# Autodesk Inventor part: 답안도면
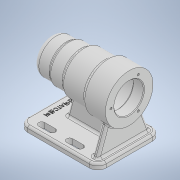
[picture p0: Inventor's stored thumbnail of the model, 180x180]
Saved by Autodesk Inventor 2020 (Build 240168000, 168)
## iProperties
Created: 2021-10
Part Number: 답안도면
Material: 일반
Document SubType Name: Modeling
Designer: user
Density: 1 g/cm^3
Appearance: 기본값
Author: user
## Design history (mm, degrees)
sketch "스케치1"
  geometry: L1 (0, 0)-(0, 34); L2 (0, 34)-(-32, 34); L3 (-32, 34)-(-32, 30); L4 (-32, 30)-(-66, 30); L5 (-66, 30)-(-66, 27); L6 (-66, 27)-(-88, 27); L7 (-88, 27)-(-88, 25); L8 (-88, 25)-(-112, 25); L9 (-112, 25)-(-112, 0); L10 (-112, 0)-(0, 0)
  constraints: 20 end point, 9 perpendicular, 1 vertical
  dimensions: "d0" = 24 distance of L7.end L8.end; "d1" = 46 distance between parallel lines of L5 L9; "d2" = 80 distance between parallel lines of L3 L9; "d3" = 112 distance between parallel lines of L1 L9; "d4" = 50 diameter of L8 L10; "d5" = 54 diameter of L6 L10; "d6" = 60 diameter of L4 L10; "d7" = 68 diameter of L2 L10
revolve "회전1" sketch "스케치1" stored, may be unused: angle "d8" = 90 deg
sketch "스케치2"
  geometry: C1 r 21 at (0, 0); 1 further point
  constraints: 1 centre point, 1 coincident
  dimensions: "d9" = 42 diameter of C1
extrude "돌출1" cut sketch "스케치2" distance "d10" = 15; taper "d11" = 0 deg
sketch "스케치3"
  geometry: C1 r 24 at (0, 0); 1 further point
  constraints: 1 centre point, 1 coincident
  dimensions: "d12" = 48 diameter of C1
extrude "돌출2" cut sketch "스케치3" distance "d13" = 54; taper "d14" = 0 deg
sketch "스케치4"
  geometry: C1 r 21 at (0, 0); 1 further point
  constraints: 1 centre point, 1 coincident
  dimensions: "d15" = 42 diameter of C1
extrude "돌출3" cut sketch "스케치4" distance "d16" = 12; taper "d17" = 0 deg
sketch "스케치5"
  geometry: C1 r 24 at (0, 0) reference; C2 r 17.5 at (0, 0); 1 further point
  constraints: 1 centre point, 1 coincident
  dimensions: "d18" = 35 diameter of C2
extrude "돌출4" cut sketch "스케치5" distance "d19" = 18; taper "d20" = 0 deg
sketch "스케치6"
  geometry: C1 r 16 at (0, 0); 1 further point
  constraints: 1 centre point, 1 coincident
  dimensions: "d21" = 32 diameter of C1
extrude "돌출5" cut sketch "스케치6" distance "d22" = 4; taper "d23" = 0 deg
sketch "스케치7"
  geometry: C1 r 21 at (0, 0) reference; C2 r 10.5 at (0, 0); 1 further point
  constraints: 1 centre point, 1 coincident
  dimensions: "d24" = 21 diameter of C2
extrude "돌출6" cut sketch "스케치7" distance "d25" = 3; taper "d26" = 0 deg
node "작업 평면1"
sketch "스케치10"
  geometry: L1 (112, 45)-(0, 45); L2 (0, 45)-(0, -45); L3 (0, -45)-(112, -45); L4 (112, -45)-(112, 45); L5 (112, 45)-(0, -45); L6 (0, 45)-(112, -45); L7 (112, 25)-(112, -25) reference; 3 further points
  constraints: 12 end point, 3 midpoint, 2 parallel, 1 horizontal, 1 horizontal alignment, 1 perpendicular, 1 point on line
  dimensions: "d28" = 112 distance of L3.end L2.end; "d29" = 90 distance of L2.end L1.end
extrude "돌출7" join sketch "스케치10" distance "d30" = 8; taper "d31" = 0 deg
sketch "스케치11"
  geometry: L1 (-85, -4)-(-8, -4); L2 (-8, -4)-(-8, 4); L3 (-8, 4)-(-85, 4); L4 (-85, 4)-(-85, -4); L5 (-85, -4)-(-8, 4); L6 (-8, -4)-(-85, 4); L7 (-112, -45)-(0, -45) reference; L8 (0, -45)-(0, 45) reference; 4 further points
  constraints: 12 end point, 4 midpoint, 2 parallel, 1 horizontal, 1 horizontal alignment, 1 perpendicular
  dimensions: "d34" = 8 distance between parallel lines of L8 L2; "d35" = 8 distance of L3.end L1.start; "d36" = 77 distance of L2.end L3.end
extrude "돌출8" join sketch "스케치11" stored distance "d37" = 8; taper "d38" = 0 deg
sketch "스케치12"
  geometry: L1 (-41, -8)-(-41, 0) reference; L2 (-41, 0)-(0, 0) reference; L3 (0, 0)-(0, 28.236) reference; L4 (8, 28.236)-(8, 0) reference; L5 (8, 0)-(49, 0) reference; L6 (49, 0)-(49, -8) reference; L7 (49, -8)-(-41, -8) reference; L8 (0, 0)-(8, 0) reference; L9 (-19.409, 37.342)-(-33, 0); L10 (49, 0)-(-41, 0) reference; C1 r 21 at (4, 62) reference; A1 r 34 centre (4, 62) between (8, 28.236) and (0, 28.236) reference; A2 r 34 centre (4, 62) between (0, 28.236) and (8, 28.236) reference; 2 further points
  constraints: 2 end point, 1 point on circle, 1 point on line
  dimensions: "d39" = 8 distance from line of L1 L9.end; "d40" = 110 deg angle of L2 L9
extrude "돌출9" join sketch "스케치12" distance "d41" = 8; taper "d42" = 0 deg
sketch "스케치14"
  geometry: L1 (-92, 33)-(-77, 33); L2 (-92, 28.5)-(-77, 28.5); L3 (-77, 37.5)-(-92, 37.5); L4 (-112, 45)-(-112, -45) reference; L5 (-52, 33)-(-37, 33); L6 (-52, 28.5)-(-37, 28.5); L7 (-37, 37.5)-(-52, 37.5); A1 r 4.5 centre (-92, 33) between (-92, 37.5) and (-92, 28.5); A2 r 4.5 centre (-77, 33) between (-77, 28.5) and (-77, 37.5); A3 r 4.5 centre (-52, 33) between (-52, 37.5) and (-52, 28.5); A4 r 4.5 centre (-37, 33) between (-37, 28.5) and (-37, 37.5); 3 further points
  constraints: 16 end point, 8 point on circle, 8 tangent, 4 centre point, 2 horizontal, 2 midpoint, 2 parallel
  dimensions: "d43" = 9 diameter of A2; "d44" = 20 distance from line of L1.start L4; "d45" = 15 distance of L1.end L1.start; "d46" = 9 diameter of A4; "d47" = 25 distance of L5.start L1.end; "d48" = 15 distance of L5.end L5.start; "d49" = 33 vertical distance of point (0, 0) point (-84.5, 33); "d50" = 33 vertical distance of point (0, 0) point (-44.5, 33)
extrude "돌출10" cut sketch "스케치14" distance "d51" = 30; taper "d52" = 0 deg
sketch "스케치16"
  geometry: C1 r 10.5 at (0, 0) reference; 2 further points
  constraints: 1 horizontal alignment
  dimensions: "d54" = 26 distance of point (0, 0) point (-26, 0)
hole "구멍1" sketch "스케치16" at (-26, 0) diameter "d55" = 3.242; stored, may be unused: countersink angle "d59" = 90 deg, drill point angle "d61" = 118 deg; dims "d56" = 8, "d57" = 4, "d58" = 2, "d60" = 11
chamfer "모따기1" distance "d65" = 1; stored, may be unused: second distance "d66" = 2, angle "d67" = 45 deg
fillet "모깎기1" dims "d68" = 3
fillet "모깎기2" dims "d69" = 0.3
fillet "모깎기3" dims "d70" = 3
fillet "모깎기4" dims "d71" = 8
fillet "모깎기5" dims "d72" = 3
feature "면 기울기1" dims angle "d73" = 15 deg
fillet "모깎기6" dims "d74" = 12
fillet "모깎기7" dims "d75" = 3
fillet "모깎기8" dims "d76" = 3
fillet "모깎기9" dims "d77" = 3
sketch "스케치17"
  geometry: L1 (-112, 33)-(-112, -33) reference; 2 further points
  constraints: 1 horizontal alignment, 1 other
  dimensions: "d78" = 12 distance from line of point (-100, 0) L1
feature "엠보싱1" sketch "스케치17" dims "d0" = 24, "d1" = 46, "d2" = 80, "d3" = 112, "d4" = 50, "d5" = 54, "d6" = 60, "d7" = 68, "d79" = 0.5, "d80" = 0
fillet "모깎기10" dims "d81" = 3
node "솔리드1"
mirror "미러1"
mirror "미러2"
pattern_circular "원형 패턴1" dims angle "d63" = 360 deg
node "절단 모서리 투영1"
feature "A9D066F2-1C7D-4E18-AEED-F7BC21143FA4" dims "d55" = 3.242, "d56" = 8, "d57" = 4, "d58" = 2, "d59" = 90 deg, "d60" = 11, "d61" = 118 deg
